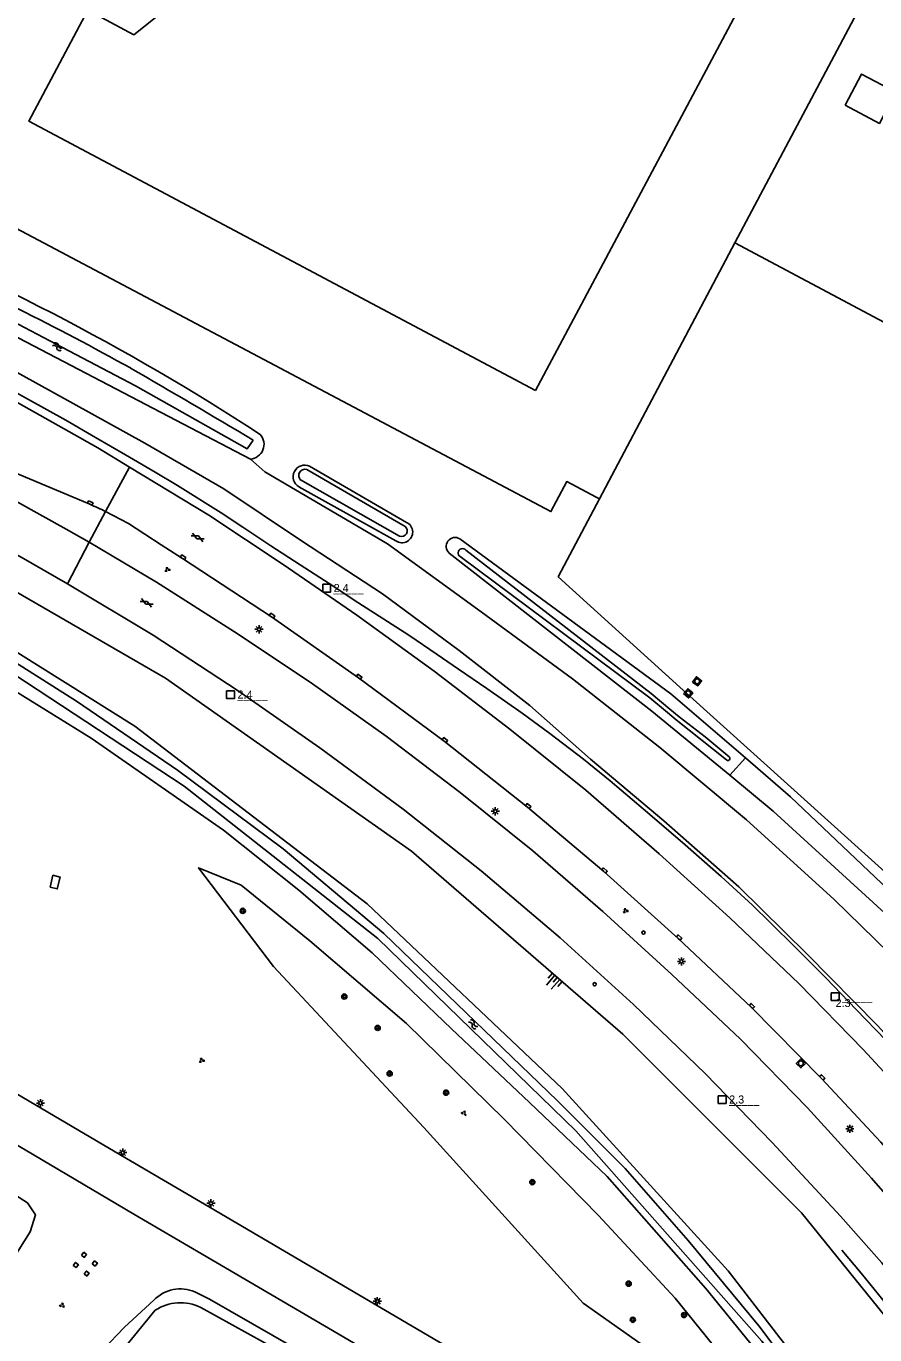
# Model space of a CAD drawing. Extents: x 136000 to 138005, y 398500 to 400500.
# Drawn here: x 136608.7 to 136740.1, y 398859.5 to 399062 of the extents above; entities that cross this region are included whole.
import ezdxf

# ---------------------------------------------------------------- set-up
doc = ezdxf.new("R2010")
doc.units = 0
for name, color, linetype in [('gg-afsc-faunaraster', 7, 'Continuous'), ('gg-afsc-hekwerk', 7, 'Continuous'), ('gg-bbg-bijgebouw', 7, 'Continuous'), ('gg-bbg-hoofdgebouw', 7, 'Continuous'), ('gg-bbg-hoogspanningsmast', 7, 'Continuous'), ('gg-knt-BGT kruinlijn', 7, 'Continuous'), ('gg-knt-bovenkant onderkant talud', 7, 'Continuous'), ('gg-knt-bronhoudergrens', 7, 'Continuous'), ('gg-knt-verharding', 7, 'Continuous'), ('gg-kntw-bovenkant insteek waterloop', 7, 'Continuous'), ('gg-kntw-greppel-droge sloot', 7, 'Continuous'), ('gg-kntw-waterlijn', 7, 'Continuous'), ('gt-anno-nummer hm paal', 7, 'Continuous'), ('gt-grn-groengrens', 7, 'Continuous'), ('gt-grn-vlakafsluiter', 7, 'Continuous'), ('gt-grn-weggrens', 7, 'Continuous'), ('gt-knt-geleideconstructie', 7, 'Continuous'), ('gt-symb-boom', 7, 'Continuous'), ('gt-symb-gesloten verharding', 7, 'Continuous'), ('gt-symb-groenvak', 7, 'Continuous'), ('gt-symb-hm paal', 7, 'Continuous'), ('gt-symb-kolk', 7, 'Continuous'), ('gt-symb-lichtmast', 7, 'Continuous'), ('gt-symb-rioolschacht', 7, 'Continuous'), ('gt-symb-talud symbool', 7, 'Continuous'), ('gt-symb-verkeersregelinstallatiepaal', 7, 'Continuous'), ('gt-symb-watersymbool', 7, 'Continuous')]:
    doc.layers.add(name, color=color, linetype=linetype)

# ---------------------------------------------------------------- blocks, each defined once
blk = doc.blocks.new('gt0-GRVAK')
at = {"layer": 'gt-symb-groenvak'}
for p, q in [((-0.11, 0.19), (-0.23, 0.24)), ((-0.18, 0.15), (0.09, 0.15)), ((-0.09, 0.21), (-0.16, 0.32)), ((-0.05, 0.21), (-0.05, 0.39)), ((0, 0.21), (0.06, 0.32)), ((0.01, 0.19), (0.13, 0.24)), ((0.26, -0.05), (0.2, 0.06)), ((0.3, -0.05), (0.3, 0.13)), ((0.35, -0.05), (0.41, 0.06)), ((-0.24, -0.23), (-0.36, -0.18)), ((-0.32, -0.26), (-0.05, -0.26)), ((-0.23, -0.21), (-0.29, -0.1)), ((-0.18, -0.2), (-0.18, -0.02)), ((-0.14, -0.21), (-0.07, -0.1)), ((-0.12, -0.23), (0, -0.18)), ((0.24, -0.07), (0.12, -0.02)), ((0.17, -0.11), (0.44, -0.11)), ((0.37, -0.07), (0.49, -0.02))]:
    blk.add_line(p, q, dxfattribs=at)
blk = doc.blocks.new('gt0-LMAST')
at = {"layer": 'gt-symb-lichtmast'}
for p, q in [((-0.18, 0.17), (-0.45, 0.44)), ((-0.01, 0.25), (-0.01, 0.62)), ((0.17, 0.17), (0.44, 0.44)), ((-0.26, 0), (-0.63, 0)), ((-0.18, -0.18), (-0.45, -0.45)), ((-0.01, -0.25), (-0.01, -0.63)), ((0.44, -0.45), (0.17, -0.18)), ((0.24, 0), (0.62, 0))]:
    blk.add_line(p, q, dxfattribs=at)
blk.add_circle((-0.01, 0), 0.25, dxfattribs=at)
blk = doc.blocks.new('gt0-BOOM')
at = {"layer": 'gt-symb-boom'}
for radius in [0.4, 0.2]:
    blk.add_circle((0, 0), radius, dxfattribs=at)
blk = doc.blocks.new('gt0-KOLK')
at = {"layer": 'gt-symb-kolk'}
blk.add_lwpolyline([(0, 0), (0.37, 0), (0.37, 0.4), (-0.38, 0.4), (-0.38, 0), (0, 0)], dxfattribs=at)
blk = doc.blocks.new('gt0-WA')
at = {"layer": 'gt-symb-watersymbool'}
for centre, start, end in [((-0.32, 0.02), 28.0725, 151.9275), ((0.43, 0.42), 208.0725, 331.9275), ((-0.32, -0.43), 28.0725, 151.9275), ((0.43, -0.03), 208.0725, 331.9275)]:
    blk.add_arc(centre, 0.425, start, end, dxfattribs=at)
blk = doc.blocks.new('gt0-GESVH1')
at = {"layer": 'gt-symb-gesloten verharding'}
for p, q in [((-0.99, -0.26), (0.01, 0.24)), ((0.01, -0.26), (-0.99, 0.24)), ((0.01, 0.24), (1.01, -0.26)), ((1.01, 0.24), (0.01, -0.26))]:
    blk.add_line(p, q, dxfattribs=at)
blk = doc.blocks.new('gt0-HMpaal')
at = {"layer": 'gt-symb-hm paal'}
blk.add_lwpolyline([(-0.6, 0.6), (0.6, 0.6), (0.6, -0.6), (-0.6, -0.6)], close=True, dxfattribs=at)
blk = doc.blocks.new('gt0-RS')
at = {"layer": 'gt-symb-rioolschacht'}
blk.add_lwpolyline([(-0.5, -0.5), (0.5, -0.5), (0.5, 0.5), (-0.5, 0.5)], close=True, dxfattribs=at)
blk.add_circle((0, 0), 0.375, dxfattribs=at)
blk = doc.blocks.new('gt0-TALUD_1')
at = {"layer": 'gt-symb-talud symbool'}
for p, q in [((-1, -1), (-1, 0)), ((-0.5, -2), (-0.5, 0)), ((0, -1), (0, 0)), ((0.5, -2), (0.5, 0)), ((1, -1), (1, 0))]:
    blk.add_line(p, q, dxfattribs=at)
blk = doc.blocks.new('gt0-VIPAAL')
at = {"layer": 'gt-symb-verkeersregelinstallatiepaal'}
blk.add_circle((0, 0), 0.25, dxfattribs=at)

msp = doc.modelspace()

# ---------------------------------------------------------------- linework, layer by layer
at = {"layer": 'gg-afsc-faunaraster'}
msp.add_lwpolyline([(136564.65, 398984.36), (136588.81, 398970.45), (136601.21, 398962.65), (136618.79, 398951.86), (136639.23, 398937.6), (136650.94, 398928.3), (136662.25, 398918.61), (136674.52, 398906.86), (136686.63, 398895.42), (136698.64, 398884), (136713.9, 398866.63), (136724.94, 398853.08), (136733.99, 398841.3)], dxfattribs=at)
at = {"layer": 'gg-afsc-hekwerk'}
for p, q in [((136718.4, 399028.53), (136748.76, 399085.7)), ((136718.4, 399028.53), (136697.43, 398988.9)), ((136795.53, 398987.4), (136718.4, 399028.53)), ((136697.43, 398988.9), (136691.03, 398976.8))]:
    msp.add_line(p, q, dxfattribs=at)
at = {"layer": 'gg-bbg-bijgebouw'}
msp.add_lwpolyline([(136735.45, 399049.8), (136740.77, 399046.99), (136743.34, 399051.84), (136738.02, 399054.64), (136735.45, 399049.8)], dxfattribs=at)
at = {"layer": 'gg-bbg-hoofdgebouw'}
msp.add_lwpolyline([(136687.53, 399005.63), (136609.14, 399047.34), (136618.26, 399064.51), (136625.39, 399060.71), (136641.18, 399073.37), (136648.26, 399069.61), (136664.05, 399082.28), (136671.09, 399078.48), (136686.89, 399091.19), (136693.86, 399087.47), (136709.8, 399100.03), (136731.58, 399088.43), (136687.53, 399005.63)], dxfattribs=at)
at = {"layer": 'gg-bbg-hoogspanningsmast'}
for points in [[(136612.41, 398928.78), (136612.86, 398930.61), (136613.97, 398930.34), (136613.52, 398928.51), (136612.41, 398928.78)], [(136617.28, 398871.81), (136617.64, 398872.26), (136618.07, 398871.91), (136617.71, 398871.46), (136617.28, 398871.81)], [(136618.93, 398870.48), (136619.29, 398870.93), (136619.73, 398870.58), (136619.37, 398870.13), (136618.93, 398870.48)], [(136616.01, 398870.23), (136616.37, 398870.68), (136616.81, 398870.33), (136616.45, 398869.88), (136616.01, 398870.23)], [(136617.67, 398868.9), (136618.03, 398869.35), (136618.46, 398869.01), (136618.1, 398868.56), (136617.67, 398868.9)]]:
    msp.add_lwpolyline(points, dxfattribs=at)
at = {"layer": 'gg-knt-BGT kruinlijn'}
for points in [[(136766.7, 398877.75), (136762.77, 398882.98), (136751.68, 398895.01), (136740.49, 398907.36), (136729.59, 398918.38), (136719.02, 398928.84), (136707.43, 398939.06), (136696.06, 398948.59), (136686.66, 398956.89), (136675.74, 398965.42), (136663.88, 398974.17), (136651.31, 398982.4), (136639.33, 398990.43), (136627.07, 398997.52), (136593.77, 399015.94), (136570.2, 399027.77), (136567.25, 399029.21)], [(136753.45, 398849.49), (136752.56, 398848.9), (136728.69, 398878.34), (136701.04, 398906.04), (136668.35, 398934.33), (136630.3, 398961.14), (136590.24, 398984.22), (136555.64, 399000.79)]]:
    msp.add_lwpolyline(points, dxfattribs=at)
at = {"layer": 'gg-knt-bovenkant onderkant talud'}
msp.add_line((136643.42, 398995.03), (136645.67, 398993.04), dxfattribs=at)
msp.add_lwpolyline([(136778.75, 398877.77), (136776.14, 398883.09), (136772.34, 398887.53), (136746.52, 398914.43), (136733.73, 398926.93), (136720.2, 398939.19), (136706.78, 398950.39), (136693.28, 398961.03), (136679.15, 398971.37), (136664.63, 398981.9), (136645.67, 398993.04)], dxfattribs=at)
at = {"layer": 'gg-knt-bronhoudergrens'}
msp.add_lwpolyline([(136779.27, 398894.02), (136745.29, 398927.82), (136709.9, 398959.72), (136691.03, 398976.8)], dxfattribs=at)
at = {"layer": 'gg-knt-verharding'}
msp.add_line((136618.45, 398982.16), (136621.01, 398986.92), dxfattribs=at)
for points in [[(136696.92, 398989.16), (136692.37, 398991.54), (136689.92, 398986.92), (136606.24, 399031.25)], [(136624.72, 398993.8), (136619.78, 398996.77), (136604.66, 399005.28), (136585.71, 399015.32), (136570.11, 399023.03), (136565.73, 399025.74)], [(136560.61, 399014.05), (136565.34, 399011.87), (136568, 399010.59), (136571.47, 399008.95), (136587.83, 399001), (136590.56, 398999.76), (136603.39, 398994.41), (136617.57, 398988.47), (136618.56, 398988.04)], [(136559.75, 399012.1), (136569.67, 399007.57), (136586.76, 398999.24), (136592.03, 398996.47), (136603.54, 398990.49), (136614.92, 398984.18), (136618.45, 398982.16)], [(136556.82, 399005.39), (136562.3, 399002.9), (136577.07, 398995.92), (136592.06, 398988.34), (136607.94, 398979.83), (136615.09, 398975.73)], [(136624.72, 398993.8), (136636.96, 398986.36), (136648.48, 398978.71), (136659.87, 398970.87), (136671.85, 398962.23), (136683.58, 398953.25), (136695.32, 398943.79), (136706.69, 398933.95), (136717.61, 398924.05), (136728.3, 398913.84), (136738.26, 398903.67), (136748.46, 398892.58), (136757.9, 398881.7), (136767.71, 398869.37)], [(136621.01, 398986.92), (136624.55, 398985.05), (136629.59, 398981.78), (136632.89, 398979.65), (136646.66, 398970.62), (136660.15, 398961.18), (136673.41, 398951.37), (136686.3, 398941.15), (136698.12, 398931.19), (136709.64, 398920.84), (136720.92, 398910.22), (136731.79, 398899.18), (136740.97, 398889.32), (136749.85, 398879.15), (136757.01, 398870.49), (136763.84, 398861.9)], [(136761.74, 398857.84), (136749.06, 398872.85), (136739.53, 398883.71), (136729.65, 398894.6), (136719.25, 398905.24), (136708.65, 398915.26), (136697.98, 398925), (136687.12, 398934.4), (136675.88, 398943.45), (136664.41, 398952.14), (136652.68, 398960.49), (136640.97, 398968.31), (136628.87, 398975.96), (136618.45, 398982.16)], [(136757.47, 398849.57), (136754.8, 398852.89), (136754, 398853.03), (136753.47, 398853.64), (136752.42, 398854.95), (136751.95, 398855.56), (136752.02, 398856.37), (136746.56, 398863.35), (136746.18, 398863.83), (136746.52, 398864.12), (136741.13, 398870.64), (136734.77, 398877.84), (136724.2, 398889.27), (136713.8, 398899.93), (136702.69, 398910.63), (136691.35, 398920.92), (136679.15, 398931.31), (136667.08, 398940.86), (136654.15, 398950.35), (136641.36, 398959.25), (136628.36, 398967.77), (136615.09, 398975.73)], [(136637.19, 398879.2), (136623.39, 398887.31), (136597.81, 398902.32), (136585.6, 398909.46), (136574.17, 398916.31), (136570.46, 398918.51)], [(136566.98, 398912.37), (136573.01, 398908.86), (136608.55, 398888.09), (136625.36, 398878.17), (136635.93, 398871.97)], [(136637.19, 398879.2), (136679.96, 398854.07), (136713.93, 398834.13), (136728.01, 398825.91), (136730.79, 398824.72)], [(136734.25, 398814.2), (136720.64, 398822.26), (136702.62, 398832.87), (136679.53, 398846.38), (136657, 398859.64), (136635.93, 398871.97)]]:
    msp.add_lwpolyline(points, dxfattribs=at)
msp.add_arc((136582.79, 398906.17), 89.34, 64.6701, 66.3998, dxfattribs=at)
at = {"layer": 'gg-kntw-bovenkant insteek waterloop'}
for p, q in [((136652.59, 398993.94), (136667.58, 398985.24)), ((136665.95, 398982.38), (136650.94, 398990.73)), ((136720.04, 398948.78), (136711.04, 398956.52)), ((136717.6, 398946.1), (136708.44, 398953.66)), ((136720.04, 398948.78), (136717.6, 398946.1))]:
    msp.add_line(p, q, dxfattribs=at)
for points in [[(136574.89, 399031.58), (136575.14, 399030.7), (136643.42, 398995.03)], [(136625.51, 398953.67), (136585.8, 398978.57), (136575.27, 398983.81)], [(136711.04, 398956.52), (136708.49, 398958.71), (136675.84, 398982.68)], [(136708.44, 398953.66), (136705.57, 398956.04), (136674.19, 398980.49)], [(136737.92, 398842.77), (136717.37, 398869.39), (136691.65, 398897.6), (136661.47, 398926.2), (136625.51, 398953.67)], [(136599.6, 398885.86), (136608.94, 398879.89), (136610.14, 398878.03), (136609.34, 398875.42), (136605.8, 398869.87)], [(136628.47, 398864.84), (136623.95, 398860.65), (136620.57, 398857.17), (136617.16, 398852.57), (136613.88, 398847.43), (136613.84, 398842.03), (136615.07, 398836.99), (136617.8, 398832.92)], [(136711.18, 398768.88), (136706.87, 398782.42), (136703.48, 398794.6), (136702.2, 398803.26), (136701.81, 398805.43), (136699.18, 398811.11), (136695.07, 398818.08), (136685.76, 398829.14), (136683.63, 398830.64), (136686.09, 398835.71), (136666.49, 398848.15), (136637.1, 398865.01), (136634.84, 398866.12)]]:
    msp.add_lwpolyline(points, dxfattribs=at)
for centre, radius, start, end in [((136440.31, 398684.52), 375.08, 56.9362, 68.3182), ((136643.24, 398997.31), 2.29, 274.295, 42.128), ((136651.84, 398992.3), 1.8, 65.4588, 240.0605), ((136666.89, 398983.74), 1.65, 235.152, 65.4101), ((136675.09, 398981.53), 1.37, 57.212, 228.9812), ((136632.57, 398860.93), 5.67, 66.3605, 136.2975)]:
    msp.add_arc(centre, radius, start, end, dxfattribs=at)
at = {"layer": 'gg-kntw-greppel-droge sloot'}
for points in [[(136779.17, 398888.93), (136762.33, 398907.93), (136745.18, 398925.5), (136727.03, 398942.77), (136720.04, 398948.78)], [(136777.67, 398887.51), (136760.22, 398906.15), (136742.8, 398923.68), (136724.33, 398940.53), (136717.6, 398946.1)]]:
    msp.add_lwpolyline(points, dxfattribs=at)
at = {"layer": 'gg-kntw-waterlijn'}
for p, q in [((136652.14, 398993.43), (136667.39, 398984.61)), ((136651.18, 398991.8), (136666.5, 398983.08)), ((136676.76, 398980.96), (136705.47, 398958.77)), ((136675.9, 398979.94), (136705.24, 398958.07)), ((136707.95, 398955.83), (136705.24, 398958.07)), ((136705.47, 398958.77), (136708.35, 398956.3)), ((136707.95, 398955.83), (136709.33, 398954.65)), ((136708.35, 398956.3), (136709.79, 398955.15)), ((136709.33, 398954.65), (136717.09, 398948.47)), ((136628.67, 398863.28), (136617.13, 398849.23))]:
    msp.add_line(p, q, dxfattribs=at)
for points in [[(136643.84, 398997.98), (136642.92, 398996.63), (136625.65, 399006.36), (136614.33, 399012.3), (136600.56, 399019.53), (136576.62, 399031.1), (136577.1, 399032.09), (136578.73, 399031.88)], [(136731.91, 398847.88), (136722.11, 398860.88), (136711.19, 398874.09), (136701.41, 398885.21), (136690.95, 398895.68), (136664.08, 398921.61), (136648.47, 398934.68), (136632.16, 398946.88), (136616.49, 398957.56), (136594.63, 398971.38), (136566.22, 398986.85), (136565.48, 398986.18), (136565.85, 398985.41), (136574.23, 398980.95), (136592.99, 398970.48), (136606.66, 398961.82), (136633.17, 398944.38), (136663.15, 398920.83), (136693.8, 398891.07), (136722.57, 398858.48), (136731.32, 398847.3), (136731.91, 398847.88)], [(136709.79, 398955.15), (136713.82, 398952.02), (136717.52, 398948.97)], [(136635.73, 398863.73), (136647.88, 398857.02), (136667.9, 398845.41), (136675.81, 398840.83)]]:
    msp.add_lwpolyline(points, dxfattribs=at)
for centre, radius, start, end in [((136412.75, 398627.32), 436.77, 60.9477, 66.0921), ((135947.68, 397833.84), 1356.41, 59.12037, 60.05064), ((136651.88, 398992.48), 0.979, 75.0232, 224.3197), ((136666.78, 398983.94), 0.903, 251.6182, 47.7008), ((136676.25, 398980.51), 0.673, 41.2954, 238.7074), ((136717.31, 398948.71), 0.332, 228.3777, 51.2814), ((136632.6, 398857.28), 7.17, 64.1512, 123.2765)]:
    msp.add_arc(centre, radius, start, end, dxfattribs=at)
at = {"layer": 'gt-grn-groengrens'}
msp.add_lwpolyline([(136717.16, 398848.72), (136718.04, 398852.64), (136716.98, 398855.47), (136709.17, 398865.13), (136697.3, 398877.95), (136682.7, 398892.87), (136667.59, 398907.67), (136652.61, 398920.48), (136642.01, 398929.07), (136635.4, 398931.78), (136646.98, 398916.47), (136670.28, 398891.56), (136694.9, 398864.39), (136717.16, 398848.72)], dxfattribs=at)
at = {"layer": 'gt-grn-vlakafsluiter'}
msp.add_line((136696.92, 398989.16), (136697.43, 398988.9), dxfattribs=at)
at = {"layer": 'gt-grn-weggrens'}
for p, q in [((136621.01, 398986.92), (136624.72, 398993.8)), ((136618.45, 398982.16), (136615.09, 398975.73))]:
    msp.add_line(p, q, dxfattribs=at)
at = {"layer": 'gt-knt-geleideconstructie'}
for points in [[(136600.92, 399008.73), (136609.06, 399004.28), (136614.84, 399001.04), (136619.46, 398998.39), (136624.08, 398995.67), (136628.67, 398993), (136632.13, 398990.95), (136638.92, 398986.71), (136642.25, 398984.49), (136646.6, 398981.6), (136651.12, 398978.68), (136655.63, 398975.76), (136660.07, 398972.85), (136667.94, 398967.76), (136672.33, 398964.78), (136675.64, 398962.53), (136680.02, 398959.53), (136685.5, 398955.71), (136689.77, 398952.58), (136694.96, 398948.6), (136699.1, 398945.22), (136704.2, 398940.9), (136710.29, 398935.68), (136716.27, 398930.44), (136721.14, 398925.96), (136723.88, 398923.28), (136727.86, 398919.39), (136732.54, 398914.69), (136737.17, 398909.86), (136741.78, 398905.07)], [(136734.97, 398872.58), (136737.95, 398869.01), (136741.32, 398864.9), (136743.77, 398861.81)]]:
    msp.add_lwpolyline(points, dxfattribs=at)

# ---------------------------------------------------------------- block references
at = {"layer": 'gt-symb-boom'}
for p in [(136642.24, 398925.1), (136657.95, 398911.84), (136663.12, 398906.98), (136664.97, 398899.92), (136673.71, 398896.96), (136687.05, 398883.11), (136701.97, 398867.4), (136710.54, 398862.54), (136702.61, 398861.81)]:
    msp.add_blockref('gt0-BOOM', p, dxfattribs=at)
at = {"layer": 'gt-symb-gesloten verharding'}
for p, rotation in [((136635.26, 398982.93), -26.565051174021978), ((136627.35, 398972.8), -26.565051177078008)]:
    msp.add_blockref('gt0-GESVH1', p, dxfattribs=dict(at, rotation=rotation))
at = {"layer": 'gt-symb-groenvak'}
for p in [(136630.54, 398977.94), (136701.47, 398925.12), (136635.86, 398901.96)]:
    msp.add_blockref('gt0-GRVAK', p, dxfattribs=at)
for p, rotation in [((136676.47, 398893.81), -44.35170201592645), ((136614.26, 398864.07), -30.54109846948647)]:
    msp.add_blockref('gt0-GRVAK', p, dxfattribs=dict(at, rotation=rotation))
at = {"layer": 'gt-symb-hm paal'}
for p in [(136655.22, 398975.05), (136640.34, 398958.57), (136733.92, 398911.84), (136716.43, 398895.89)]:
    msp.add_blockref('gt0-HMpaal', p, dxfattribs=at)
at = {"layer": 'gt-symb-kolk'}
for p, rotation in [((136618.56, 398988.04), -23.51455667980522), ((136632.89, 398979.65), -32.80060096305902), ((136646.66, 398970.62), -33.24493724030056), ((136660.15, 398961.18), -34.977932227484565), ((136673.41, 398951.37), -36.50328298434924), ((136686.3, 398941.15), -38.382457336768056), ((136698.12, 398931.19), -40.17242341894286), ((136709.64, 398920.84), -41.91906411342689), ((136720.92, 398910.22), -43.25692965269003), ((136731.79, 398899.18), -45.48623256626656)]:
    msp.add_blockref('gt0-KOLK', p, dxfattribs=dict(at, rotation=rotation))
at = {"layer": 'gt-symb-lichtmast'}
for p in [(136644.76, 398968.69), (136681.33, 398940.52), (136710.13, 398917.28), (136610.93, 398895.35), (136736.22, 398891.37), (136623.67, 398887.69), (136637.32, 398879.84), (136663.07, 398864.69)]:
    msp.add_blockref('gt0-LMAST', p, dxfattribs=at)
at = {"layer": 'gt-symb-rioolschacht'}
for p, rotation in [((136712.56, 398960.63), -36.6635924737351), ((136711.17, 398958.78), -40.414765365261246), ((136728.61, 398901.49), 135.48623256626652)]:
    msp.add_blockref('gt0-RS', p, dxfattribs=dict(at, rotation=rotation))
at = {"layer": 'gt-symb-talud symbool', "xscale": 0.999625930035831, "yscale": 0.9996259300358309, "rotation": -40.86240641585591}
msp.add_blockref('gt0-TALUD_1', (136690.91, 398914.8), dxfattribs=at)
at = {"layer": 'gt-symb-verkeersregelinstallatiepaal'}
for p in [(136704.26, 398921.75), (136696.7, 398913.74)]:
    msp.add_blockref('gt0-VIPAAL', p, dxfattribs=at)
at = {"layer": 'gt-symb-watersymbool'}
for p, rotation in [((136613.52, 399012.46), -26.949580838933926), ((136677.85, 398907.58), -40.98653320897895)]:
    msp.add_blockref('gt0-WA', p, dxfattribs=dict(at, rotation=rotation))

# ---------------------------------------------------------------- texts
at = {"layer": 'gt-anno-nummer hm paal'}
for s, p in [('2.4', (136656.3, 398974.45)), ('2.4', (136641.42, 398957.96)), ('2.3', (136733.99, 398910.22)), ('2.3', (136717.52, 398895.28))]:
    msp.add_text(s, height=1.25, dxfattribs=at).set_placement(p)
at = {"layer": 'gt-symb-hm paal'}
for p in [(136656.3, 398974.45), (136641.42, 398957.96), (136735, 398911.24), (136717.52, 398895.28)]:
    msp.add_text('_____', height=1.25, dxfattribs=at).set_placement(p)

doc.saveas('drawing.dxf')
